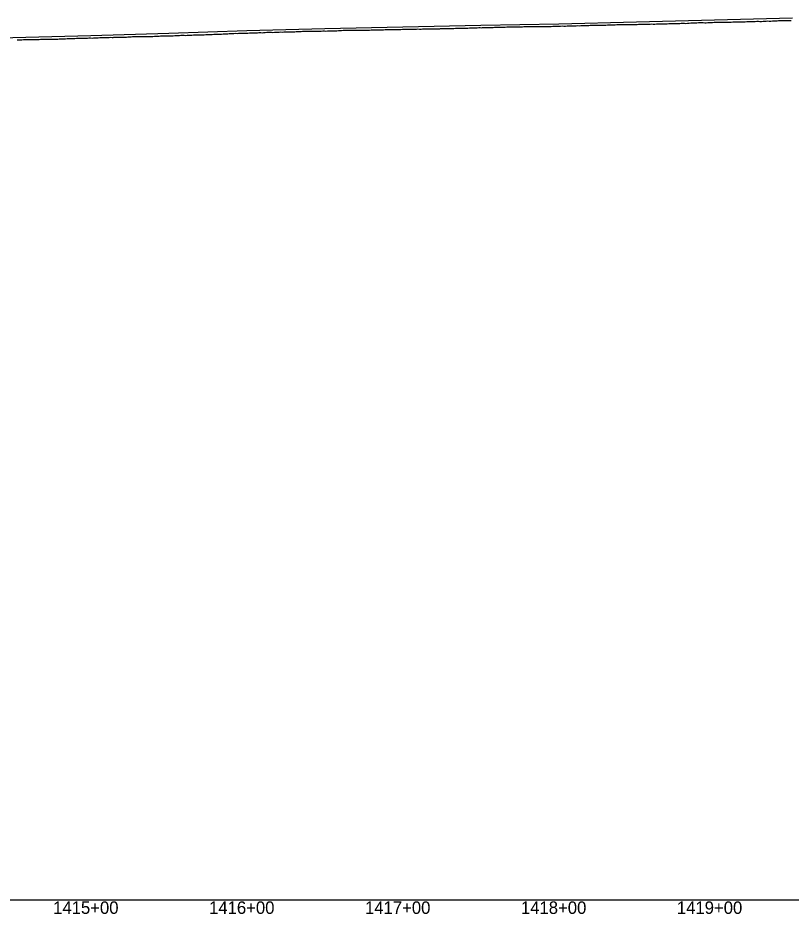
# Model space of a CAD drawing. Extents: x -3793 to 50787, y -1075 to 6138.
# Drawn here: x 28779 to 29275, y 2991 to 3566 of the extents above; entities that cross this region are included whole.
import ezdxf

# ---------------------------------------------------------------- set-up
doc = ezdxf.new("R2010")
doc.units = 0
for name, color, linetype in [('RD_DDB_Profile_EX', 7, 'Continuous'), ('RD_DDB_Profile_PR', 7, 'Continuous'), ('RD_DDB_StaTX', 7, 'Continuous'), ('RD_GPK_Profile_Cell', 7, 'Continuous')]:
    doc.layers.add(name, color=color, linetype=linetype)

msp = doc.modelspace()

# ---------------------------------------------------------------- linework, layer by layer
at = {"layer": 'RD_DDB_Profile_EX'}
for points in [[(29169.17358, 3561.36996), (29170.174036, 3561.317405), (29171.174491, 3561.321615), (29172.164715, 3561.36975), (29173.165178, 3561.419305), (29174.16564, 3561.416815), (29175.165673, 3561.465825), (29176.166134, 3561.514315), (29177.166595, 3561.555835), (29178.166628, 3561.56289), (29179.167088, 3561.611385), (29180.167546, 3561.561135), (29180.53347, 3561.5617), (29181.534538, 3561.61025), (29182.534538, 3561.65905), (29183.534537, 3561.65913), (29184.535603, 3561.658955), (29185.535603, 3561.756395), (29186.536667, 3561.70622), (29187.536667, 3561.706305), (29188.536667, 3561.75775), (29189.537729, 3561.757715), (29190.537729, 3561.806385), (29191.538789, 3561.806395), (29192.538789, 3561.80647), (29193.538789, 3561.806545), (29194.539847, 3561.808145), (29195.539847, 3561.906725), (29196.540903, 3561.95692), (29197.540903, 3562.05392), (29198.541957, 3562.099365), (29199.541957, 3562.051025), (29200.541958, 3562.052685), (29201.54301, 3562.0513), (29202.54301, 3562.101375), (29203.54406, 3562.148325), (29204.544061, 3562.24674), (29205.544061, 3562.298485), (29206.545109, 3562.34706), (29207.54511, 3562.15737), (29208.546156, 3562.25272), (29209.546157, 3562.29929), (29210.546157, 3562.397615), (29211.547202, 3562.49266), (29212.547202, 3562.49453), (29213.548245, 3562.49495), (29214.548245, 3562.54319), (29215.548246, 3562.59144), (29216.549286, 3562.688105), (29217.549287, 3562.69006), (29218.550326, 3562.59244), (29219.550326, 3562.45018), (29220.550327, 3562.404075), (29221.551364, 3562.73731), (29222.551365, 3562.73935), (29223.5524, 3562.741945), (29224.552401, 3562.79002), (29225.552401, 3562.8381), (29226.553435, 3562.83465), (29227.553435, 3562.88677), (29228.554467, 3562.88954), (29229.554468, 3562.889615), (29230.554424, 3562.983515), (29231.555452, 3562.936315), (29232.555453, 3562.938515), (29233.55648, 3562.985045), (29234.556481, 3562.98512), (29235.556482, 3562.987355), (29236.557507, 3562.988255), (29237.557508, 3563.03833), (29238.558531, 3563.13258), (29239.558532, 3563.082655), (29240.544641, 3563.037195), (29241.545385, 3563.03823), (29242.545437, 3563.085945), (29243.54618, 3563.134695), (29244.546197, 3563.134765), (29245.546975, 3563.18345), (29246.546992, 3563.27877), (29247.547008, 3563.28359), (29248.53824, 3563.284745), (29249.538294, 3563.23475), (29250.489816, 3563.28108), (29250.95726, 3563.329255), (29251.957298, 3563.424455), (29252.957353, 3563.476895), (29253.957391, 3563.479405), (29254.957749, 3563.43059), (29255.957787, 3563.43066), (29256.957842, 3563.478185), (29257.95788, 3563.62331), (29258.957918, 3563.62586), (29259.957956, 3563.675935), (29260.958011, 3563.633345), (29261.958369, 3563.629625), (29262.958407, 3563.677185), (29263.958462, 3563.6797), (29264.958501, 3563.772245), (29265.958539, 3563.869815), (29266.958577, 3563.919895), (29267.958632, 3563.874905)], [(29267.958632, 3563.874905), (29268.95899, 3563.926115), (29269.959028, 3563.976185), (29270.959083, 3563.926185), (29271.959122, 3563.973715), (29272.95916, 3563.97379), (29273.959198, 3563.976405), (29274.959253, 3564.028945)], [(28979.65908, 3557.336175), (28980.659931, 3557.284875), (28981.650984, 3557.33533), (28982.651992, 3557.334825), (28983.652976, 3557.431715), (28984.653823, 3557.52967), (28985.654808, 3557.52909), (28986.655656, 3557.57866), (28987.65664, 3557.775095), (28988.657488, 3557.824655), (28989.132544, 3557.776615), (28989.658456, 3557.725475), (28990.649537, 3557.723915), (28991.650355, 3557.77269), (28992.651297, 3557.82002), (28993.652115, 3557.822635), (28994.652941, 3557.821715), (28995.902005, 3557.820855), (28996.654687, 3557.81958), (28997.65561, 3557.76884), (28998.656395, 3557.768765), (28999.65718, 3557.7682), (29000.648061, 3557.71902), (29001.648845, 3557.818455), (29002.671467, 3557.81836), (29003.650385, 3557.818085), (29004.65114, 3557.86825), (29005.651894, 3557.91796), (29006.652649, 3557.9681), (29007.653403, 3557.9178), (29008.654158, 3557.917485), (29009.654906, 3557.917135), (29010.655549, 3557.966185), (29011.656276, 3558.06447), (29012.657005, 3558.063985), (29013.647806, 3558.063825), (29014.648532, 3558.11369), (29015.649127, 3558.114945), (29016.210391, 3558.11466), (29016.649841, 3558.11434), (29017.650538, 3558.163275), (29018.651237, 3558.113255), (29019.651934, 3558.162205), (29020.652631, 3558.26089), (29021.65333, 3558.260205), (29022.653898, 3558.26151), (29022.979852, 3558.26184), (29023.654448, 3558.262715), (29024.65499, 3558.2632), (29025.655532, 3558.363245), (29026.655994, 3558.36402), (29027.656532, 3558.3152), (29028.647158, 3558.366805), (29029.749314, 3558.41726), (29030.64822, 3558.41779), (29031.648865, 3558.4667), (29032.649383, 3558.51636), (29033.6499, 3558.367425), (29034.650418, 3558.3195), (29035.650935, 3558.568595), (29036.65145, 3558.52021), (29037.651943, 3558.520085), (29038.652437, 3558.56992), (29039.652931, 3558.56975), (29040.653425, 3558.620115), (29041.653939, 3558.61944), (29042.654431, 3558.569815), (29043.288238, 3558.60174), (29043.654915, 3558.62014), (29044.655386, 3558.66919), (29045.655856, 3558.620515), (29046.656327, 3558.62127), (29047.656799, 3558.670295), (29048.647385, 3558.719855), (29049.647858, 3558.7212), (29050.057699, 3558.741765), (29050.648316, 3558.77069), (29051.648768, 3558.770675), (29052.649346, 3558.819625), (29053.649797, 3558.86961), (29054.650247, 3558.869065), (29055.650699, 3558.82014), (29056.827161, 3558.82894), (29057.651476, 3558.86942), (29058.651908, 3558.869225), (29059.652341, 3558.96796), (29060.652773, 3558.967775), (29061.653204, 3558.96759), (29062.653636, 3559.01741), (29063.654067, 3559.06671), (29064.654481, 3559.115855), (29065.654896, 3559.06648), (29066.65531, 3559.06706), (29067.655725, 3559.06667), (29068.656139, 3559.214475), (29069.646642, 3559.214525), (29070.647048, 3559.263705), (29071.647444, 3559.313185), (29072.64784, 3559.31306), (29073.648235, 3559.362525), (29074.648631, 3559.411625)], [(29074.648631, 3559.411625), (29075.649027, 3559.41041), (29076.649422, 3559.360255), (29077.135546, 3559.384305), (29077.64981, 3559.409975), (29078.650132, 3559.45928), (29079.650517, 3559.508585), (29080.650902, 3559.507895), (29081.651286, 3559.5572), (29082.65167, 3559.55651), (29083.905008, 3559.56846), (29084.65243, 3559.60499), (29085.652802, 3559.653865), (29086.653174, 3559.653155), (29087.653546, 3559.652385), (29088.653917, 3559.70147), (29089.644293, 3559.650635), (29090.67447, 3559.70254), (29091.645361, 3559.797925), (29092.645994, 3559.846405), (29093.646629, 3559.894565), (29094.647263, 3559.89304), (29095.647897, 3559.891585), (29096.648531, 3559.83998), (29097.649172, 3559.938055), (29098.650296, 3559.984175), (29099.650957, 3559.933085), (29100.651618, 3559.980425), (29101.652279, 3559.979025), (29102.652946, 3559.97821), (29103.653608, 3560.025895), (29104.213393, 3560.0283), (29105.168566, 3560.028915), (29106.16872, 3560.07853), (29107.167833, 3560.03127), (29108.167987, 3560.03183), (29109.16814, 3560.031945), (29110.167262, 3560.083725), (29111.167434, 3560.084565), (29112.167687, 3560.03483), (29113.166906, 3560.086665), (29114.167159, 3560.136885), (29115.167406, 3560.08747), (29116.166623, 3560.089465), (29117.166877, 3560.13905), (29117.752317, 3560.16825), (29118.167172, 3560.189155), (29119.166489, 3560.1906), (29120.166844, 3560.140555), (29121.167198, 3560.19024), (29122.166514, 3560.242135), (29123.166864, 3560.242105), (29124.167218, 3560.241555), (29124.521779, 3560.259765), (29125.1666, 3560.292755), (29126.167058, 3560.342265), (29127.167515, 3560.39178), (29128.166932, 3560.49269), (29129.16739, 3560.442425), (29130.167848, 3560.44219), (29131.29124, 3560.549205), (29132.167809, 3560.592185), (29133.168371, 3560.591485), (29134.167892, 3560.54268), (29135.168454, 3560.592), (29136.169017, 3560.591595), (29137.168537, 3560.642505), (29138.169112, 3560.6913), (29139.169781, 3560.64069), (29140.169401, 3560.741445), (29141.17007, 3560.740865), (29142.170739, 3560.78938), (29143.170366, 3560.790445), (29144.171036, 3560.7399), (29144.830164, 3560.772275), (29145.171742, 3560.789345), (29146.171476, 3560.889865), (29147.172254, 3560.938865), (29148.173023, 3560.937875), (29149.172759, 3560.988005), (29150.173537, 3560.98697), (29151.174314, 3561.035485), (29151.599626, 3561.056995), (29152.174113, 3561.085045), (29153.175001, 3561.03466), (29154.175888, 3561.034435), (29155.175633, 3561.034265), (29156.176503, 3561.083055), (29157.177382, 3561.13242), (29158.369087, 3561.240945), (29159.178201, 3561.278945), (29160.179191, 3561.22806), (29161.179152, 3561.178885), (29162.180143, 3561.27531), (29163.180105, 3561.37548), (29164.181097, 3561.37538), (29165.182075, 3561.423895), (29166.182094, 3561.374745), (29167.183141, 3561.37235), (29168.173547, 3561.36987), (29169.17358, 3561.36996)], [(28789.662594, 3551.808225), (28790.665549, 3551.80755), (28791.668365, 3551.808615), (28792.818153, 3551.824775), (28793.664192, 3551.90557), (28794.666931, 3551.90645), (28795.659796, 3551.905455), (28796.662535, 3551.956335), (28797.665414, 3551.959785), (28798.668293, 3552.0075), (28799.661009, 3552.058275), (28800.663821, 3552.00993), (28801.666489, 3552.010675), (28802.659557, 3552.0594), (28803.661948, 3552.11014), (28804.66476, 3552.10895), (28805.667568, 3552.157815), (28806.66047, 3552.256995), (28807.662937, 3552.30433), (28808.665535, 3552.256155), (28809.65839, 3552.306475), (28810.660859, 3552.355135), (28811.663457, 3552.404315), (28812.666055, 3552.404805), (28813.126538, 3552.427305), (28813.659002, 3552.45455), (28814.661276, 3552.457385), (28815.663805, 3552.505055), (28816.666476, 3552.550945), (28817.659246, 3552.55364), (28818.661524, 3552.555145), (28819.896, 3552.615255), (28820.656908, 3552.652275), (28821.659371, 3552.701085), (28822.661726, 3552.69933), (28823.664189, 3552.70059), (28824.656878, 3552.79931), (28825.659471, 3552.796435), (28826.665462, 3552.74899), (28827.664238, 3552.796825), (28828.656843, 3552.84542), (28829.659237, 3552.895295), (28830.661768, 3552.941195), (28831.654147, 3552.9899), (28832.656544, 3553.04288), (28833.659058, 3553.08988), (28834.66139, 3553.04049), (28835.653901, 3553.040985), (28836.656172, 3553.086865), (28837.658501, 3553.135605), (28838.660833, 3553.185235), (28839.653454, 3553.134715), (28840.204385, 3553.161985), (28840.655588, 3553.184225), (28841.657719, 3553.235485), (28842.659853, 3553.23671), (28843.661984, 3553.28797), (28844.654296, 3553.28907), (28845.656237, 3553.38836), (28846.658371, 3553.391545), (28846.973847, 3553.39194), (28847.66046, 3553.39369), (28848.662667, 3553.39182), (28849.654933, 3553.44169), (28850.656796, 3553.540525), (28851.658866, 3553.592575), (28852.660939, 3553.64352), (28853.743309, 3553.644575), (28854.655245, 3553.64514), (28855.657156, 3553.64531), (28856.659168, 3553.69491), (28857.661177, 3553.69685), (28858.66319, 3553.69998), (28859.655187, 3553.74948), (28860.657191, 3553.750215), (28861.659141, 3553.799565), (28862.661224, 3553.798365), (28863.663173, 3553.79894), (28864.664875, 3553.80199), (28865.657062, 3553.803725), (28866.659012, 3553.901815), (28867.282232, 3553.933285), (28867.66094, 3553.95232), (28868.662832, 3553.90526), (28869.664724, 3553.954355), (28870.656734, 3554.051545), (28871.658626, 3554.09938), (28872.660518, 3554.14846), (28873.66241, 3554.150085), (28874.051694, 3554.15022), (28874.664268, 3554.150305), (28875.656351, 3554.202925), (28876.657928, 3554.201775), (28877.659897, 3554.24889), (28878.661733, 3554.25029), (28879.663435, 3554.25482), (28880.821156, 3554.320995), (28881.656913, 3554.402675), (28882.658693, 3554.45126), (28883.660341, 3554.504265), (28884.662121, 3554.552805)], [(28884.662121, 3554.552805), (28885.663769, 3554.505845), (28886.665549, 3554.457205), (28887.657184, 3554.55731), (28888.658911, 3554.655565), (28889.660505, 3554.609965), (28890.662232, 3554.658185), (28891.663827, 3554.70962), (28892.665549, 3554.7094), (28893.666832, 3554.71395), (28894.658846, 3554.760385), (28895.660388, 3554.76161), (28896.662063, 3554.764255), (28897.663605, 3554.76714), (28898.664962, 3554.865025), (28899.666499, 3554.916305), (28900.658488, 3554.96409), (28901.129541, 3554.98822), (28901.660004, 3555.015225), (28902.661628, 3555.016125), (28903.66312, 3555.06391), (28904.664414, 3555.160025), (28905.665901, 3555.25933), (28906.667523, 3555.260375), (28907.899003, 3555.26279), (28908.66091, 3555.26545), (28909.662348, 3555.31301), (28910.663918, 3555.358915), (28911.665024, 3555.36302), (28912.666597, 3555.412195), (28913.658355, 3555.509625), (28914.668464, 3555.55885), (28915.661315, 3555.56275), (28916.662705, 3555.561715), (28917.664226, 3555.65743), (28918.665616, 3555.756355), (28919.666811, 3555.66032), (28920.658525, 3555.760795), (28921.660036, 3555.81136), (28922.661379, 3555.860165), (28923.662854, 3555.81055), (28924.664197, 3555.907775), (28925.665672, 3555.95817), (28926.666698, 3555.95859), (28927.658352, 3556.010515), (28928.207388, 3556.038165), (28928.659674, 3556.059255), (28929.661104, 3556.107845), (28930.662402, 3556.111205), (28931.6637, 3556.10986), (28932.664997, 3556.16009), (28933.666295, 3556.20873), (28934.657719, 3556.305685), (28934.97685, 3556.257945), (28935.658987, 3556.160415), (28936.660241, 3556.25424), (28937.661495, 3556.30736), (28938.662882, 3556.401225), (28939.664135, 3556.40426), (28940.665389, 3556.407295), (28941.746311, 3556.440835), (28942.657853, 3556.31007), (28943.659198, 3556.45375), (28944.660413, 3556.50497), (28945.661625, 3556.554785), (28946.662836, 3556.55604), (28947.664048, 3556.60442), (28948.655658, 3556.60244), (28949.656552, 3556.60342), (28950.657723, 3556.65166), (28951.658893, 3556.701275), (28952.660197, 3556.699195), (28953.661368, 3556.798805), (28954.662539, 3556.799695), (28955.285235, 3556.767975), (28955.653942, 3556.750395), (28956.65507, 3556.799765), (28957.656086, 3556.89617), (28958.65722, 3556.94435), (28959.658351, 3556.99376), (28960.659482, 3556.9943), (28961.660613, 3557.04369), (28962.054697, 3557.04275), (28962.661856, 3557.04121), (28963.653151, 3557.040305), (28964.65424, 3557.089485), (28965.655131, 3557.18668), (28966.656223, 3557.13687), (28967.657316, 3557.08702), (28968.824158, 3557.13781), (28969.659337, 3557.13695), (28970.660259, 3557.13863), (28971.651501, 3557.18746), (28972.652235, 3557.237235), (28973.653291, 3557.236205), (28974.654347, 3557.285175), (28975.655267, 3557.2868), (28976.656287, 3557.236415), (28977.657174, 3557.335145), (28978.658194, 3557.383905), (28979.65908, 3557.336175)], [(28778.660522, 3551.60711), (28779.279229, 3551.638935), (28779.663178, 3551.65856), (28780.666208, 3551.659495), (28781.659499, 3551.658865), (28782.662108, 3551.708775), (28783.665137, 3551.7083), (28784.668031, 3551.70956), (28785.661041, 3551.806065), (28786.048691, 3551.80589), (28786.664025, 3551.805485), (28787.666841, 3551.806525), (28788.659778, 3551.75716), (28789.662594, 3551.808225)]]:
    msp.add_lwpolyline(points, dxfattribs=at)
at = {"layer": 'RD_DDB_Profile_PR'}
msp.add_lwpolyline([(28275.9, 3549.716), (28325.9, 3549.7055), (28375.9, 3549.4785), (28425.9, 3549.4055), (28475.9, 3549.397), (28525.9, 3549.755), (28575.9, 3550.0965), (28625.9, 3550.713), (28675.9, 3551.601), (28725.9, 3552.483), (28775.9, 3553.169), (28825.9, 3554.3855), (28875.9, 3555.8025), (28925.9, 3557.5585), (28975.9, 3558.875), (29025.9, 3559.9635), (29075.9, 3560.998), (29125.9, 3561.9285), (29175.9, 3563.101), (29225.9, 3564.437), (29275.9, 3565.6315)], dxfattribs=at)
at = {"layer": 'RD_GPK_Profile_Cell'}
msp.add_line((1000, 3000), (46549.603806, 3000), dxfattribs=at)

# ---------------------------------------------------------------- texts
at = {"layer": 'RD_DDB_StaTX'}
for s, p in [('1415+00', (28801.687695, 2991)), ('1415+00', (28801.695471, 2991)), ('1416+00', (28901.687695, 2991)), ('1416+00', (28901.695471, 2991)), ('1417+00', (29001.687695, 2991)), ('1417+00', (29001.695471, 2991)), ('1418+00', (29101.687695, 2991)), ('1418+00', (29101.695471, 2991)), ('1419+00', (29201.687695, 2991)), ('1419+00', (29201.695471, 2991))]:
    msp.add_text(s, height=8, dxfattribs=at).set_placement(p)

doc.saveas('drawing.dxf')
